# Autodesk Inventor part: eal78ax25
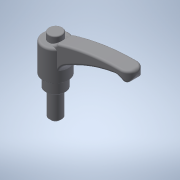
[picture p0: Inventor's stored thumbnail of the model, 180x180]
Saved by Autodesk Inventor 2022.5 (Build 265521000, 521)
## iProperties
Created: 2016-12
Part Number: eal78ax25
Material: 一般
Document SubType Name: Modeling
Designer: imaocorp
Density: 1 g/cm^3
Appearance: 既定
Author: imaocorp
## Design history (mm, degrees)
node "eal78ax25.x_t1"
node "eal78ax25"
node "Base1"
